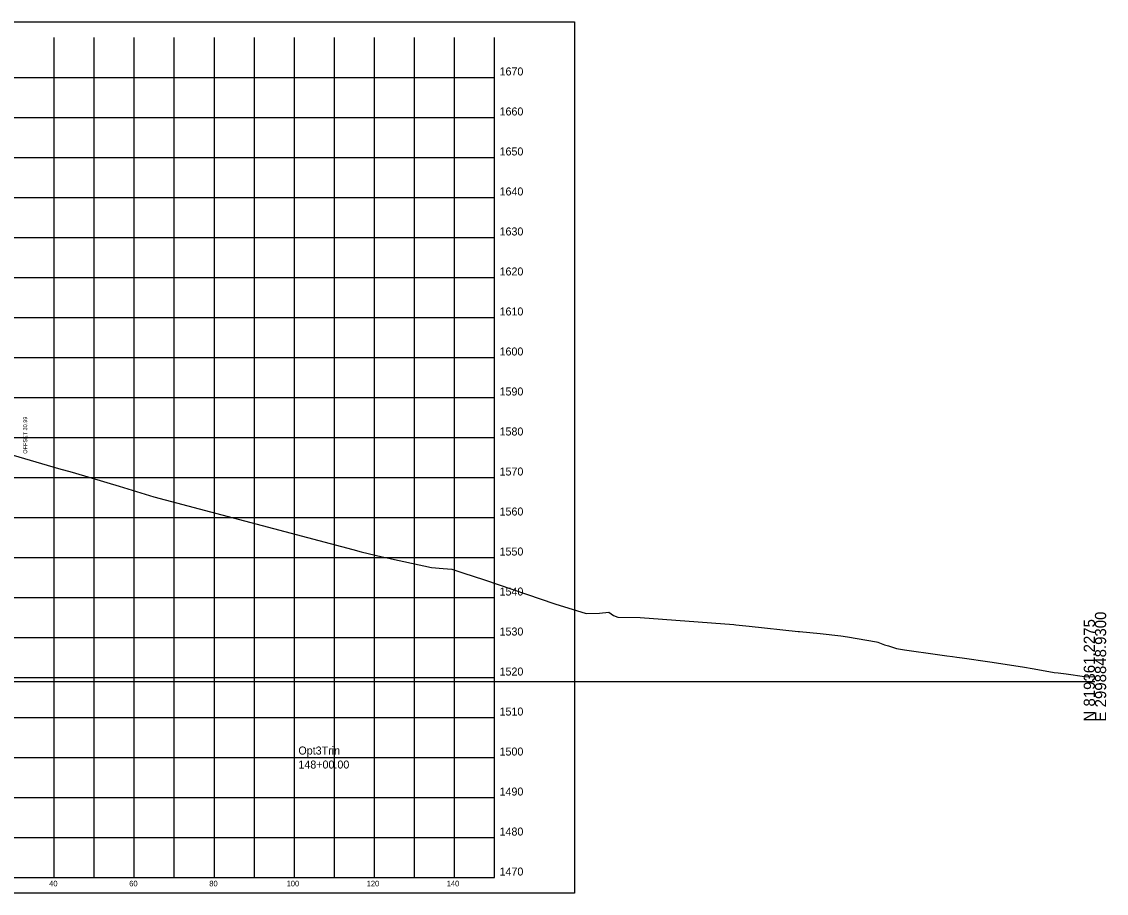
# Model space of a CAD drawing. Extents: x -26 to 603, y -10 to 4805.
# Drawn here: x 331.9 to 602.8, y 2447.1 to 2664.9 of the extents above; entities that cross this region are included whole.
import ezdxf

# ---------------------------------------------------------------- set-up
doc = ezdxf.new("R2010")
doc.units = 0
for name, color, linetype in [('DESIGN - SHEET - Corner Text', 7, 'Continuous'), ('DESIGN - SHEET - Light Grid', 7, 'Continuous'), ('DESIGN - SHEET - Linework', 7, 'Continuous'), ('DESIGN - SHEET - Plot Shape', 7, 'Continuous'), ('DESIGN - TYPICAL - Slope Tie Text', 7, 'Continuous'), ('DESIGN - TYPICAL - Warning Text', 7, 'Continuous'), ('SURVEY - GROUND - Top of Ground', 7, 'Continuous')]:
    doc.layers.add(name, color=color, linetype=linetype)

msp = doc.modelspace()

# ---------------------------------------------------------------- linework, layer by layer
at = {"layer": 'DESIGN - SHEET - Light Grid'}
msp.add_line((300, 2500), (600, 2500), dxfattribs=at)
at = {"layer": 'DESIGN - SHEET - Linework'}
for p, q in [((340, 2451), (340, 2661)), ((350, 2451), (350, 2661)), ((360, 2451), (360, 2661)), ((370, 2451), (370, 2661)), ((380, 2451), (380, 2661)), ((390, 2451), (390, 2661)), ((400, 2451), (400, 2661)), ((410, 2451), (410, 2661)), ((420, 2451), (420, 2661)), ((430, 2451), (430, 2661)), ((440, 2451), (440, 2661)), ((150, 2651), (450, 2651)), ((150, 2641), (450, 2641)), ((150, 2631), (450, 2631)), ((150, 2621), (450, 2621)), ((150, 2611), (450, 2611)), ((150, 2601), (450, 2601)), ((150, 2591), (450, 2591)), ((150, 2581), (450, 2581)), ((150, 2571), (450, 2571)), ((150, 2561), (450, 2561)), ((150, 2551), (450, 2551)), ((150, 2541), (450, 2541)), ((150, 2531), (450, 2531)), ((150, 2521), (450, 2521)), ((150, 2511), (450, 2511)), ((150, 2501), (450, 2501)), ((150, 2491), (450, 2491)), ((150, 2481), (450, 2481)), ((150, 2471), (450, 2471)), ((150, 2461), (450, 2461))]:
    msp.add_line(p, q, dxfattribs=at)
msp.add_lwpolyline([(150, 2661), (150, 2451), (450, 2451), (450, 2661)], dxfattribs=at)
at = {"layer": 'DESIGN - SHEET - Plot Shape'}
msp.add_lwpolyline([(130, 2664.94), (470, 2664.94), (470, 2447.06), (130, 2447.06)], close=True, dxfattribs=at)
at = {"layer": 'SURVEY - GROUND - Top of Ground'}
msp.add_line((364.84, 2546.18), (414.56, 2533.01), dxfattribs=at)
for points in [[(309.21, 2562.62), (341.05, 2553.23), (344.51, 2552.33), (349.25, 2550.94), (356.19, 2548.8), (364.84, 2546.18)], [(414.56, 2533.01), (416.65, 2532.44), (421.89, 2531.21), (422.85, 2530.97), (424.28, 2530.64), (434.23, 2528.51), (437.2, 2528.24), (439.37, 2528.11), (442.11, 2527.2), (447.47, 2525.38), (465.05, 2519.44), (472.88, 2517.03), (476.24, 2517.12), (478.56, 2517.32), (479.7, 2516.52), (480.78, 2516.08), (486.38, 2516), (509.81, 2514.22), (510.3, 2514.18), (513.61, 2513.83), (525.82, 2512.52), (526.22, 2512.47), (528.79, 2512.26), (531.33, 2511.99), (536.48, 2511.41), (538.14, 2511.15), (545.43, 2509.92), (545.77, 2509.82), (547.02, 2509.31), (547.42, 2509.21), (548.42, 2508.92), (550.41, 2508.26), (552.43, 2507.9), (554.21, 2507.68), (558.89, 2506.99), (562.98, 2506.4), (564.39, 2506.23), (565.49, 2506.08), (566.83, 2505.95), (573.72, 2504.89), (581.92, 2503.64), (584.8, 2503.2), (589.83, 2502.29), (590.8, 2502.18), (592.77, 2501.9), (597.37, 2501.26), (600, 2501.19)]]:
    msp.add_lwpolyline(points, dxfattribs=at)

# ---------------------------------------------------------------- texts
at = {"layer": 'DESIGN - SHEET - Corner Text'}
for s, height, p in [('1670', 2, (451.25, 2651.5)), ('1660', 2, (451.25, 2641.5)), ('1650', 2, (451.25, 2631.5)), ('1640', 2, (451.25, 2621.5)), ('1630', 2, (451.25, 2611.5)), ('1620', 2, (451.25, 2601.5)), ('1610', 2, (451.25, 2591.5)), ('1600', 2, (451.25, 2581.5)), ('1590', 2, (451.25, 2571.5)), ('1580', 2, (451.25, 2561.5)), ('1570', 2, (451.25, 2551.5)), ('1560', 2, (451.25, 2541.5)), ('1550', 2, (451.25, 2531.5)), ('1540', 2, (451.25, 2521.5)), ('1530', 2, (451.25, 2511.5)), ('1520', 2, (451.25, 2501.5)), ('1510', 2, (451.25, 2491.5)), ('1500', 2, (451.25, 2481.5)), ('1490', 2, (451.25, 2471.5)), ('1480', 2, (451.25, 2461.5)), ('1470', 2, (451.25, 2451.5)), ('40', 1.4, (338.74, 2448.8)), ('60', 1.4, (358.74, 2448.8)), ('80', 1.4, (378.74, 2448.8)), ('100', 1.4, (398.06, 2448.8)), ('120', 1.4, (418.06, 2448.8)), ('140', 1.4, (438.06, 2448.8))]:
    msp.add_text(s, height=height, dxfattribs=at).set_placement(p)
at = {"layer": 'DESIGN - SHEET - Light Grid'}
for s, p in [('N 819361.2275', (600, 2490)), ('E 2998848.9300', (602.8, 2490))]:
    msp.add_text(s, height=2.8, rotation=90, dxfattribs=at).set_placement(p)
at = {"layer": 'DESIGN - TYPICAL - Slope Tie Text'}
msp.add_text('OFFSET 30.99', height=1, rotation=90, dxfattribs=at).set_placement((333.24, 2556.94))
at = {"layer": 'DESIGN - TYPICAL - Warning Text'}
for s, p in [('Opt3Trin', (401, 2481.75)), ('148+00.00', (401, 2478.25))]:
    msp.add_text(s, height=2, dxfattribs=at).set_placement(p)

doc.saveas('drawing.dxf')
